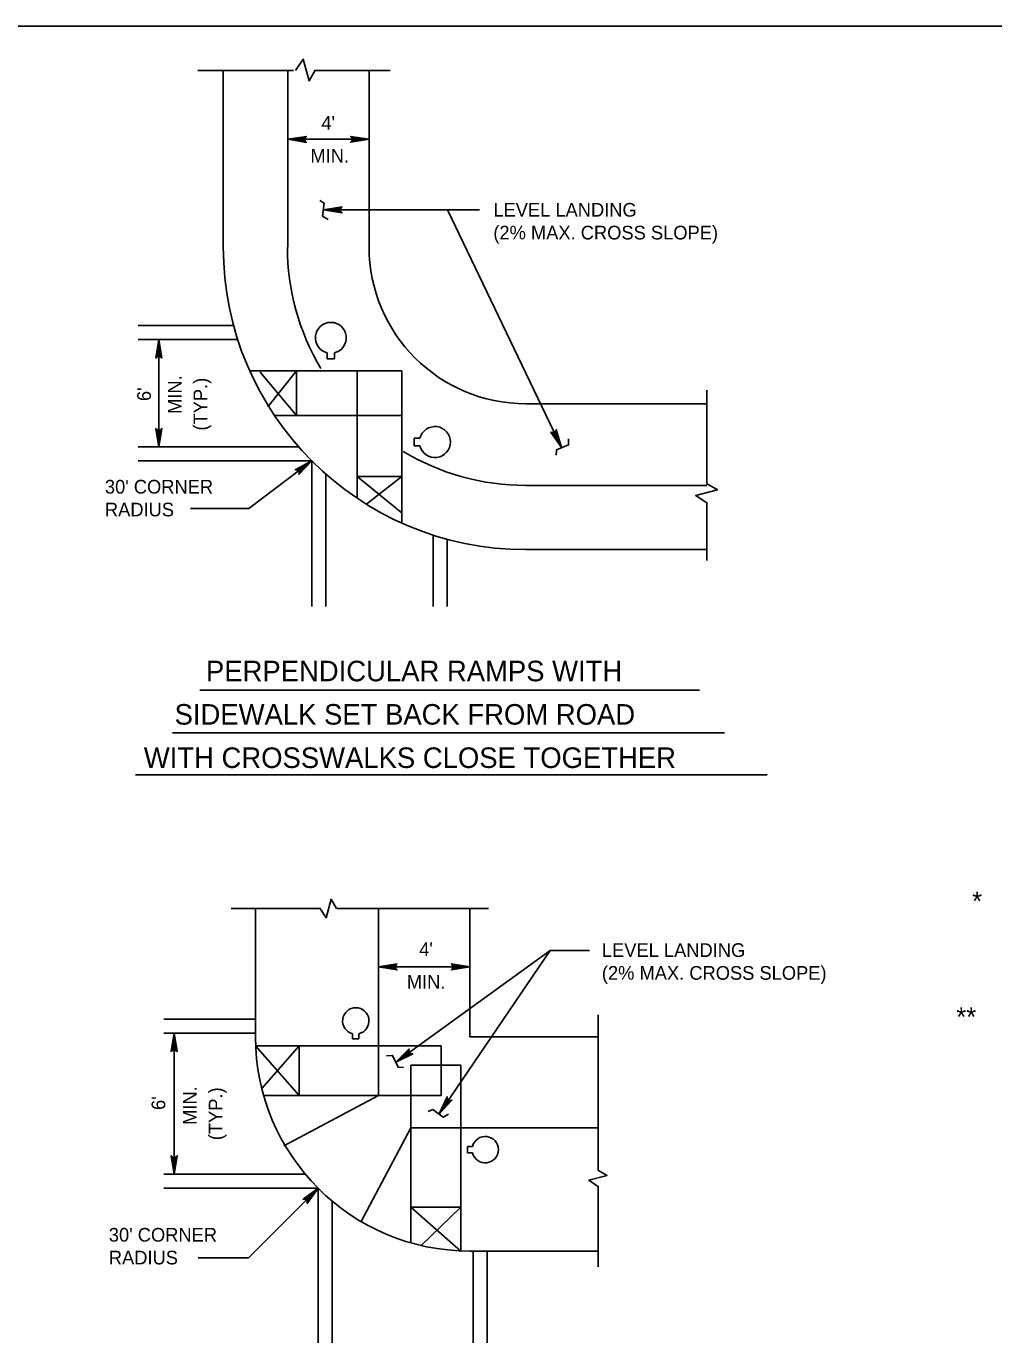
# Model space of a CAD drawing. Extents: x -344 to 940, y 22 to 1233.
# Drawn here: x 398.4 to 610.5, y 312.6 to 601.2 of the extents above; entities that cross this region are included whole.
import ezdxf

# ---------------------------------------------------------------- set-up
doc = ezdxf.new("R2010")
doc.units = 0
doc.layers.add('1', color=7, linetype='Continuous')
doc.layers.add('2', color=7, linetype='Continuous')

msp = doc.modelspace()

# ---------------------------------------------------------------- linework, layer by layer
at = {"layer": '1'}
msp.add_line((75.86, 601.17), (861.86, 601.17), dxfattribs=at)
at = {"layer": '2'}
for p, q in [((457, 591.48), (435.99, 591.48)), ((441.58, 591.48), (441.58, 552.79)), ((455.74, 552.79), (455.74, 591.48)), ((478.16, 591.48), (461.63, 591.48)), ((473.55, 591.48), (473.55, 552.79)), ((473.55, 576.4), (455.74, 576.4)), ((463.58, 560.94), (497.74, 560.94)), ((490.74, 560.94), (515.74, 508.84)), ((443.85, 535.57), (422.94, 535.57)), ((444.76, 532.5), (422.94, 532.5)), ((427.45, 508.96), (427.45, 532.5)), ((464.33, 529.59), (464.33, 528.29)), ((464.33, 528.29), (465.99, 528.29)), ((465.99, 528.29), (465.99, 529.59)), ((480.74, 525.62), (447.4, 525.62)), ((457.63, 515.83), (449.7, 525.35)), ((457.63, 525.62), (451.34, 517.78)), ((457.63, 525.62), (457.63, 515.83)), ((470.95, 525.62), (470.95, 497.71)), ((480.74, 525.62), (480.74, 492.28)), ((547.58, 501), (547.58, 521.42)), ((547.58, 518.43), (507.91, 518.43)), ((480.74, 515.83), (452.83, 515.83)), ((483.41, 509.22), (483.41, 510.87)), ((483.41, 510.87), (484.71, 510.87)), ((458.12, 508.96), (422.94, 508.96)), ((484.71, 509.22), (483.41, 509.22)), ((461.01, 505.89), (422.94, 505.89)), ((447.19, 495.49), (461.01, 505.89)), ((461.01, 505.89), (461.01, 473.99)), ((464.08, 503.01), (464.08, 473.99)), ((480.74, 502.52), (470.95, 502.52)), ((470.95, 502.52), (480.8, 494.46)), ((480.74, 502.52), (473.03, 496.5)), ((547.58, 500.53), (507.91, 500.53)), ((547.58, 484.09), (547.58, 496.76)), ((447.19, 495.49), (434.37, 495.49)), ((487.61, 489.64), (487.61, 473.99)), ((490.68, 488.74), (490.68, 473.99)), ((547.58, 486.46), (507.91, 486.46)), ((545.97, 455.68), (436.4, 455.68)), ((551.49, 446.27), (430.47, 446.27)), ((560.81, 437.06), (422.33, 437.06)), ((443.3, 407.82), (462.83, 407.82)), ((448.63, 407.82), (448.63, 379.68)), ((466.44, 407.82), (499.73, 407.82)), ((475.63, 407.82), (475.63, 366.77)), ((495.63, 407.82), (495.63, 379.69)), ((513.27, 398.62), (479.44, 374.09)), ((513.27, 398.62), (488.9, 362.81)), ((521.87, 398.62), (513.27, 398.62)), ((495.63, 394.99), (475.63, 394.99)), ((523.75, 350.5), (523.75, 384.47)), ((448.63, 383.53), (428.55, 383.53)), ((448.63, 380.46), (428.55, 380.46)), ((430.79, 349.53), (430.79, 380.46)), ((469.92, 380.35), (469.92, 379.25)), ((469.92, 379.25), (471.33, 379.25)), ((471.33, 379.25), (471.33, 380.35)), ((523.75, 379.69), (495.63, 379.69)), ((489.36, 377.69), (448.63, 377.69)), ((458.24, 366.77), (448.63, 377.69)), ((458.24, 377.69), (450.11, 368.42)), ((458.24, 377.69), (458.24, 366.77)), ((489.36, 377.69), (489.36, 366.77)), ((482.71, 373.42), (482.71, 334.5)), ((493.63, 373.42), (482.71, 373.42)), ((493.63, 373.42), (493.63, 332.7)), ((489.36, 366.77), (450.44, 366.77)), ((475.63, 366.77), (454.89, 355.79)), ((482.71, 359.69), (471.84, 339.16)), ((523.75, 359.69), (482.71, 359.69)), ((495.11, 354.22), (495.11, 355.63)), ((495.11, 355.63), (496.22, 355.63)), ((496.22, 354.22), (495.11, 354.22)), ((459.58, 349.53), (428.55, 349.53)), ((462.39, 346.46), (428.55, 346.46)), ((462.39, 346.46), (447.14, 331.21)), ((462.39, 346.46), (462.39, 312.62)), ((523.75, 329.26), (523.75, 346.9)), ((465.46, 343.65), (465.46, 312.62)), ((493.63, 342.31), (482.71, 342.31)), ((482.71, 342.31), (493.63, 332.7)), ((493.63, 342.31), (484.89, 333.84)), ((523.75, 332.7), (495.61, 332.7)), ((496.4, 332.7), (496.4, 312.62)), ((499.47, 332.7), (499.47, 312.62)), ((447.14, 331.21), (436.09, 331.21))]:
    msp.add_line(p, q, dxfattribs=at)
for points in [[(457.43, 591.46), (459.11, 593.94), (460.38, 589.2), (461.74, 591.57)], [(459.6, 575.91), (459.46, 576.19), (455.74, 576.4), (459.6, 575.91), (459.8, 575.74), (455.74, 576.4), (459.46, 576.58), (459.59, 576.86), (455.74, 576.4), (459.8, 577.04), (459.59, 576.86)], [(469.69, 576.88), (469.83, 576.6), (473.55, 576.4), (469.69, 576.88), (469.49, 577.05), (473.55, 576.4), (469.83, 576.21), (469.7, 575.94), (473.55, 576.4), (469.49, 575.75), (469.7, 575.94)], [(464.57, 558.84), (463.35, 559.53), (463.71, 562.38), (462.77, 563.02)], [(467.44, 560.46), (467.3, 560.74), (463.58, 560.94), (467.44, 560.46), (467.64, 560.29), (463.58, 560.94), (467.29, 561.12), (467.43, 561.4), (463.58, 560.94), (467.64, 561.58), (467.43, 561.4)], [(426.97, 528.64), (427.24, 528.78), (427.45, 532.5), (426.97, 528.64), (426.8, 528.44), (427.45, 532.5), (427.63, 528.79), (427.91, 528.65), (427.45, 532.5), (428.09, 528.44), (427.91, 528.65)], [(427.93, 512.82), (427.65, 512.68), (427.45, 508.96), (427.93, 512.82), (428.1, 513.02), (427.45, 508.96), (427.27, 512.67), (426.99, 512.81), (427.45, 508.96), (426.81, 513.02), (426.99, 512.81)], [(514.51, 512.53), (514.32, 512.28), (515.74, 508.84), (514.51, 512.53), (514.57, 512.78), (515.74, 508.84), (513.97, 512.11), (513.66, 512.11), (515.74, 508.84), (513.4, 512.22), (513.66, 512.11)], [(517.24, 510.77), (517.29, 509.42), (514.64, 508.32), (514.55, 507.18)], [(457.63, 503.96), (457.91, 503.82), (461.01, 505.89), (457.63, 503.96), (457.37, 503.97), (461.01, 505.89), (458.15, 503.51), (458.21, 503.21), (461.01, 505.89), (458.15, 502.94), (458.21, 503.21)], [(547.66, 496.64), (545.18, 498.32), (549.91, 499.59), (547.55, 500.95)], [(462.72, 407.89), (464.16, 405.78), (465.23, 409.81), (466.39, 407.79)], [(479.49, 394.5), (479.34, 394.78), (475.63, 394.99), (479.49, 394.5), (479.69, 394.34), (475.63, 394.99), (479.34, 395.17), (479.48, 395.45), (475.63, 394.99), (479.69, 395.63), (479.48, 395.45)], [(491.77, 395.47), (491.91, 395.19), (495.63, 394.99), (491.77, 395.47), (491.57, 395.64), (495.63, 394.99), (491.91, 394.81), (491.78, 394.53), (495.63, 394.99), (491.57, 394.34), (491.78, 394.53)], [(430.31, 376.6), (430.58, 376.75), (430.79, 380.46), (430.31, 376.6), (430.14, 376.41), (430.79, 380.46), (430.97, 376.75), (431.25, 376.61), (430.79, 380.46), (431.43, 376.41), (431.25, 376.61)], [(477.35, 375.47), (478.7, 375.58), (479.92, 372.99), (481.06, 372.95)], [(482.85, 375.97), (482.57, 376.11), (479.44, 374.09), (482.85, 375.97), (483.11, 375.95), (479.44, 374.09), (482.34, 376.42), (482.29, 376.73), (479.44, 374.09), (482.35, 377), (482.29, 376.73)], [(491.47, 365.73), (491.16, 365.77), (488.9, 362.81), (491.47, 365.73), (491.72, 365.8), (488.9, 362.81), (490.83, 365.98), (490.68, 366.25), (488.9, 362.81), (490.65, 366.53), (490.68, 366.25)], [(490.97, 362.74), (489.82, 362.02), (487.54, 363.75), (486.52, 363.26)], [(431.27, 353.39), (430.99, 353.24), (430.79, 349.53), (431.27, 353.39), (431.44, 353.58), (430.79, 349.53), (430.61, 353.24), (430.33, 353.37), (430.79, 349.53), (430.15, 353.58), (430.33, 353.37)], [(523.82, 346.79), (521.71, 348.22), (525.74, 349.3), (523.73, 350.45)], [(459.32, 344.07), (459.62, 343.97), (462.39, 346.46), (459.32, 344.07), (459.06, 344.05), (462.39, 346.46), (459.89, 343.7), (459.99, 343.41), (462.39, 346.46), (459.98, 343.13), (459.99, 343.41)]]:
    msp.add_lwpolyline(points, dxfattribs=at)
for centre, radius, start, end in [((507.91, 552.79), 66.33, 180, 270), ((507.91, 552.79), 52.26, 180, 210.6115), ((507.91, 552.79), 34.36, 180, 270), ((465.16, 532.88), 3.4, 284.1014, 255.8986), ((488, 510.04), 3.4, 194.1014, 165.8986), ((507.91, 552.79), 52.26, 239.0766, 270), ((470.63, 383.15), 2.89, 284.1014, 255.8986), ((495.61, 379.68), 46.98, 180, 270), ((499.02, 354.93), 2.89, 194.1014, 165.8986)]:
    msp.add_arc(centre, radius, start, end, dxfattribs=at)

# ---------------------------------------------------------------- texts
for s, height, p in [("4'", 3, (463.07, 578.5)), ('MIN.', 3, (460.68, 571.31)), ('LEVEL LANDING', 3, (500.79, 559.45)), ('(2% MAX. CROSS SLOPE)', 3, (500.79, 554.45)), ("30' CORNER", 3, (415.62, 498.75)), ('RADIUS', 3, (415.62, 493.75)), ('PERPENDICULAR RAMPS WITH', 4.5, (437.78, 457.6)), ('SIDEWALK SET BACK FROM ROAD', 4.5, (430.9, 448.1)), ('WITH CROSSWALKS CLOSE TOGETHER', 4.5, (424.15, 438.6)), ('*', 4.2, (605.78, 407.31)), ("4'", 3, (484.53, 397.36)), ('LEVEL LANDING', 3, (524.59, 397.17)), ('(2% MAX. CROSS SLOPE)', 3, (524.59, 392.17)), ('MIN.', 3, (481.82, 390.22)), ('**', 4.2, (602.3, 381.94)), ("30' CORNER", 3, (416.48, 334.77)), ('RADIUS', 3, (416.48, 329.77))]:
    msp.add_text(s, height=height, dxfattribs=at).set_placement(p)
for s, p in [('MIN.', (432.42, 516.21)), ('(TYP.)', (438.06, 512.55)), ("6'", (425.71, 519.02)), ('MIN.', (435.76, 360.36)), ('(TYP.)', (441.4, 357)), ("6'", (428.86, 363.63))]:
    msp.add_text(s, height=3, rotation=90, dxfattribs=at).set_placement(p)

doc.saveas('drawing.dxf')
